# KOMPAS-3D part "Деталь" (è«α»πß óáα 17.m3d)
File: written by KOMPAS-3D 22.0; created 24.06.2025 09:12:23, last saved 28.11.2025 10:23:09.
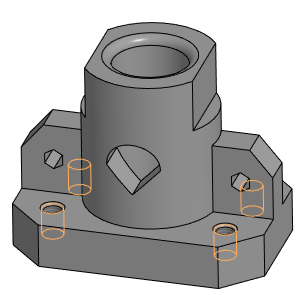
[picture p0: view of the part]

Document properties: Автор: alymovy@yandex.ru; Организация: HP; Полное имя файла: C:\Для ноута\Инженерная графика\ППЭ 2025-2026\Варианты 1-38\Вариант 17 Cura\Корпус вар 17.m3d

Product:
- Part/product: Деталь
    Материал: Полиамид П-12Б-20 ТУ 6-05-898-73 (density 1020 kg/m3)
    Масса: 0.542287

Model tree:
1. Эскиз:1
2. Элемент выдавливания:1
     Расстояние 2 = 25
3. Фаска:1  (with: Элемент выдавливания:1)
     Угол = 45; Длина 1 = 20; Длина 2 = 20
4. Эскиз:2  (with: Элемент выдавливания:1)
5. Элемент выдавливания:2
     Расстояние 1 = 85
6. Эскиз:3  (with: Фаска:1, Элемент выдавливания:1)
7. Ребро жесткости:1
     Толщина стенки 1 = 18; Толщина стенки 2 = 1
8. Зеркальный массив:1
9. Экземпляр ( 1 )
10. Экземпляр ( 2 )  (with: Ребро жесткости:1)
11. Эскиз:4  (with: Элемент выдавливания:2)
12. Элемент выдавливания:3
     Расстояние 2 = 110
13. Скругление:1  (with: Элемент выдавливания:3)
     Радиус = 5
14. Эскиз:5  (with: Элемент выдавливания:2)
15. Элемент выдавливания:4
     Расстояние 1 = 47
16. Эскиз:6  (with: Элемент выдавливания:1)
17. Элемент выдавливания:5
     Расстояние 1 = 47
18. Эскиз:7  (with: Элемент выдавливания:1, Элемент выдавливания:2)
19. Отверстие:1  (with: Элемент выдавливания:1, Ребро жесткости:1)  (labels: M12)
     Глубина выреза = 18; Диаметр отверстия = 10.1056; Угол конуса дна = 118; Расстояние 1 = -17; Расстояние 2 = 22; Диаметр зенковки = 13.3056; Глубина зенковки = 1.6; Угол зенковки = 90
20. M12  (labels: cil0_24705-2004 coarse)
     Длина резьбы = 16; Шаг резьбы = 1.75; Номинальный диаметр резьбы = 12
21. Зеркальный массив:2  (with: Экземпляр ( 1 ), Экземпляр ( 2 ), Отверстие:1)
22. Зеркальный массив:3  (with: Экземпляр ( 1 ), Экземпляр ( 2 ), Зеркальный массив:2, Отверстие:1)
23. Экземпляр ( 2 )  (with: Отверстие:1)
24. Скругление:2  (with: Элемент выдавливания:3)  (labels: Полиамид П-12Б-20 ТУ 6-05-898-73)
     Радиус = 5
